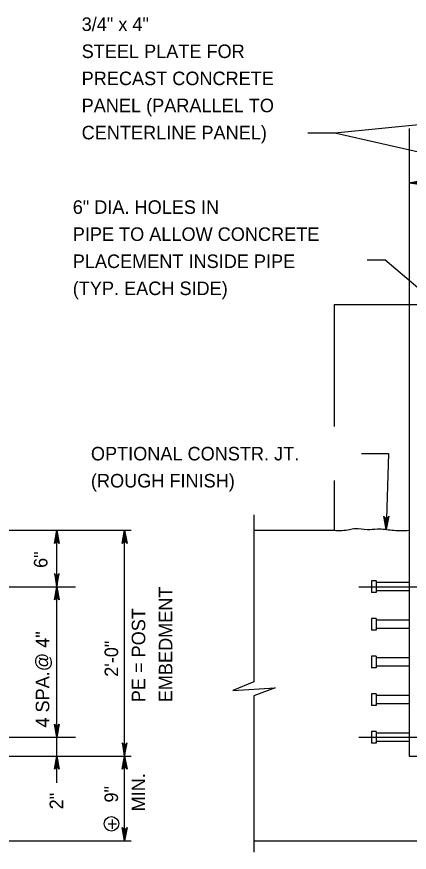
# Model space of a CAD drawing. Extents: x 3475 to 6558, y -3780 to 1166.
# Drawn here: x 4944.3 to 5033.3, y -2741.6 to -2552.1 of the extents above; entities that cross this region are included whole.
import ezdxf

# ---------------------------------------------------------------- set-up
doc = ezdxf.new("R2010")
doc.units = 0
doc.layers.add('1', color=7, linetype='Continuous')

msp = doc.modelspace()

# ---------------------------------------------------------------- linework, layer by layer
at = {"layer": '1'}
for p, q in [((5016.45, -2578.46), (5041.25, -2576)), ((5033.33, -2577.44), (5033.33, -2719.79)), ((5010.3, -2578.46), (5016.45, -2578.46)), ((5016.45, -2578.46), (5056.51, -2587.47)), ((5023.76, -2607.24), (5027.77, -2607.24)), ((5049.8, -2626.04), (5027.77, -2607.24)), ((5016.26, -2617.39), (5016.26, -2645.07)), ((5016.26, -2617.39), (5033.33, -2617.39)), ((5033.33, -2617.39), (5076, -2617.39)), ((5022.48, -2651.17), (5028.63, -2651.17)), ((5028.63, -2651.17), (5028.12, -2668.4)), ((5016.26, -2657.26), (5016.26, -2668.59)), ((4998.1, -2665.05), (4998.1, -2702.94)), ((4940.22, -2668.59), (4970.24, -2668.59)), ((4953.4, -2725.87), (4953.4, -2668.59)), ((4968.76, -2738.99), (4968.76, -2668.59)), ((4998.1, -2668.59), (5016.26, -2668.59)), ((4776.48, -2681.39), (4957.63, -2681.39)), ((5021.89, -2681.39), (5166, -2681.39)), ((5024.8, -2680.06), (5024.8, -2682.72)), ((5025.82, -2680.06), (5024.8, -2680.06)), ((5025.82, -2680.06), (5025.82, -2682.72)), ((5033.33, -2680.46), (5025.82, -2680.46)), ((5025.82, -2682.72), (5024.8, -2682.72)), ((5033.33, -2682.32), (5025.82, -2682.32)), ((5024.8, -2688.59), (5024.8, -2691.26)), ((5025.82, -2688.59), (5024.8, -2688.59)), ((5025.82, -2688.59), (5025.82, -2691.26)), ((5033.33, -2688.99), (5025.82, -2688.99)), ((5025.82, -2691.26), (5024.8, -2691.26)), ((5033.33, -2690.86), (5025.82, -2690.86)), ((5024.8, -2697.12), (5024.8, -2699.79)), ((5025.82, -2697.12), (5024.8, -2697.12)), ((5025.82, -2697.12), (5025.82, -2699.79)), ((5033.33, -2697.52), (5025.82, -2697.52)), ((5025.82, -2699.79), (5024.8, -2699.79)), ((5033.33, -2699.39), (5025.82, -2699.39)), ((4998.1, -2706.14), (4998.1, -2741.63)), ((5024.8, -2705.65), (5024.8, -2708.32)), ((5025.82, -2705.65), (5024.8, -2705.65)), ((5025.82, -2705.65), (5025.82, -2708.32)), ((5033.33, -2706.05), (5025.82, -2706.05)), ((5025.82, -2708.32), (5024.8, -2708.32)), ((5033.33, -2707.92), (5025.82, -2707.92)), ((4807.65, -2715.52), (4957.63, -2715.52)), ((5021.89, -2715.52), (5166, -2715.52)), ((5024.8, -2714.19), (5024.8, -2716.85)), ((5025.82, -2714.19), (5024.8, -2714.19)), ((5025.82, -2714.19), (5025.82, -2716.85)), ((5033.33, -2714.59), (5025.82, -2714.59)), ((5025.82, -2716.85), (5024.8, -2716.85)), ((5033.33, -2716.46), (5025.82, -2716.46)), ((4832.38, -2719.79), (4970.24, -2719.79)), ((5033.33, -2719.79), (5076, -2719.79)), ((4909.66, -2738.99), (4970.24, -2738.99)), ((4998.1, -2738.99), (5112.02, -2738.99))]:
    msp.add_line(p, q, dxfattribs=at)
for points in [[(5033.33, -2589.76), (5036.31, -2589.2), (5036.08, -2589.36), (5035.97, -2589.56), (5035.93, -2589.76), (5035.97, -2589.96), (5036.08, -2590.16), (5036.31, -2590.32), (5033.33, -2589.76), (5036.08, -2590.16), (5035.97, -2589.96), (5033.33, -2589.76), (5035.93, -2589.76), (5035.97, -2589.56), (5033.33, -2589.76), (5036.08, -2589.36)], [(5028.12, -2668.4), (5027.56, -2665.42), (5027.72, -2665.65), (5027.92, -2665.76), (5028.12, -2665.8), (5028.32, -2665.76), (5028.52, -2665.65), (5028.68, -2665.42), (5028.12, -2668.4), (5028.52, -2665.65), (5028.32, -2665.76), (5028.12, -2668.4), (5028.12, -2665.8), (5027.92, -2665.76), (5028.12, -2668.4), (5027.72, -2665.65)], [(4953.4, -2668.59), (4953.96, -2671.57), (4953.8, -2671.34), (4953.6, -2671.22), (4953.4, -2671.19), (4953.2, -2671.22), (4953, -2671.34), (4952.84, -2671.57), (4953.4, -2668.59), (4953, -2671.34), (4953.2, -2671.22), (4953.4, -2668.59), (4953.4, -2671.19), (4953.6, -2671.22), (4953.4, -2668.59), (4953.8, -2671.34)], [(4968.76, -2668.59), (4969.32, -2671.57), (4969.16, -2671.34), (4968.96, -2671.22), (4968.76, -2671.19), (4968.56, -2671.22), (4968.36, -2671.34), (4968.2, -2671.57), (4968.76, -2668.59), (4968.36, -2671.34), (4968.56, -2671.22), (4968.76, -2668.59), (4968.76, -2671.19), (4968.96, -2671.22), (4968.76, -2668.59), (4969.16, -2671.34)], [(4953.4, -2681.39), (4953.96, -2678.41), (4953.8, -2678.64), (4953.6, -2678.76), (4953.4, -2678.79), (4953.2, -2678.76), (4953, -2678.64), (4952.84, -2678.41), (4953.4, -2681.39), (4953, -2678.64), (4953.2, -2678.76), (4953.4, -2681.39), (4953.4, -2678.79), (4953.6, -2678.76), (4953.4, -2681.39), (4953.8, -2678.64)], [(4953.4, -2681.39), (4953.96, -2684.37), (4953.8, -2684.14), (4953.6, -2684.02), (4953.4, -2683.99), (4953.2, -2684.02), (4953, -2684.14), (4952.84, -2684.37), (4953.4, -2681.39), (4953, -2684.14), (4953.2, -2684.02), (4953.4, -2681.39), (4953.4, -2683.99), (4953.6, -2684.02), (4953.4, -2681.39), (4953.8, -2684.14)], [(4998.1, -2702.94), (4993.3, -2704.89), (5002.9, -2704.31), (4998.1, -2706.14)], [(4953.4, -2715.52), (4952.84, -2712.54), (4953, -2712.77), (4953.2, -2712.89), (4953.4, -2712.92), (4953.6, -2712.89), (4953.8, -2712.77), (4953.96, -2712.54), (4953.4, -2715.52), (4953.8, -2712.77), (4953.6, -2712.89), (4953.4, -2715.52), (4953.4, -2712.92), (4953.2, -2712.89), (4953.4, -2715.52), (4953, -2712.77)], [(4968.76, -2719.79), (4969.32, -2716.81), (4969.16, -2717.04), (4968.96, -2717.15), (4968.76, -2717.19), (4968.56, -2717.15), (4968.36, -2717.04), (4968.2, -2716.81), (4968.76, -2719.79), (4968.36, -2717.04), (4968.56, -2717.15), (4968.76, -2719.79), (4968.76, -2717.19), (4968.96, -2717.15), (4968.76, -2719.79), (4969.16, -2717.04)], [(4953.4, -2719.79), (4953.96, -2722.77), (4953.8, -2722.54), (4953.6, -2722.42), (4953.4, -2722.39), (4953.2, -2722.42), (4953, -2722.54), (4952.84, -2722.77), (4953.4, -2719.79), (4953, -2722.54), (4953.2, -2722.42), (4953.4, -2719.79), (4953.4, -2722.39), (4953.6, -2722.42), (4953.4, -2719.79), (4953.8, -2722.54)], [(4968.76, -2719.79), (4969.32, -2722.77), (4969.16, -2722.54), (4968.96, -2722.42), (4968.76, -2722.39), (4968.56, -2722.42), (4968.36, -2722.54), (4968.2, -2722.77), (4968.76, -2719.79), (4968.36, -2722.54), (4968.56, -2722.42), (4968.76, -2719.79), (4968.76, -2722.39), (4968.96, -2722.42), (4968.76, -2719.79), (4969.16, -2722.54)], [(4968.76, -2738.99), (4968.2, -2736.01), (4968.36, -2736.24), (4968.56, -2736.36), (4968.76, -2736.39), (4968.96, -2736.36), (4969.16, -2736.24), (4969.32, -2736.01), (4968.76, -2738.99), (4969.16, -2736.24), (4968.96, -2736.36), (4968.76, -2738.99), (4968.76, -2736.39), (4968.56, -2736.36), (4968.76, -2738.99), (4968.36, -2736.24)]]:
    msp.add_lwpolyline(points, dxfattribs=at)
msp.add_circle((4965.78, -2735.17), 1.65, dxfattribs=at)
msp.add_spline([(5016.26, -2668.59), (5019.79, -2668.41), (5021.03, -2668.16), (5023.76, -2668.41), (5026.12, -2668.27), (5027.78, -2668.37), (5031.08, -2668.66), (5033.33, -2668.59)], degree=3, dxfattribs=at)

# ---------------------------------------------------------------- texts
for s, height, p in [('3/4" x 4"', 3.072, (4959.03, -2555.33)), ('STEEL PLATE FOR ', 3.072, (4959.03, -2561.47)), ('PRECAST CONCRETE', 3.072, (4959.03, -2567.62)), ('PANEL (PARALLEL TO', 3.072, (4959.03, -2573.76)), ('CENTERLINE PANEL)', 3.072, (4959.03, -2579.91)), ('6" DIA. HOLES IN ', 3.072, (4957.01, -2596.81)), ('PIPE TO ALLOW CONCRETE', 3.072, (4957.01, -2602.95)), ('PLACEMENT INSIDE PIPE', 3.072, (4957.01, -2609.1)), ('(TYP. EACH SIDE)', 3.072, (4957.01, -2615.24)), ('OPTIONAL CONSTR. JT.', 3.072, (4961.13, -2652.74)), ('(ROUGH FINISH)', 3.072, (4961.13, -2658.88)), ('+', 3.07, (4964.77, -2736.71))]:
    msp.add_text(s, height=height, dxfattribs=at).set_placement(p)
for s, p in [('6"', (4951.27, -2677.13)), ('EMBEDMENT', (4979.59, -2707.59)), ('PE = POST', (4973.45, -2707.59)), ('4 SPA.@ 4"', (4951.68, -2713.34)), ('2\'-0"', (4967.3, -2701.81)), ('MIN.', (4973.43, -2732.35)), ('9"', (4967.28, -2730.34)), ('2"', (4954.84, -2731.89))]:
    msp.add_text(s, height=3.072, rotation=90, dxfattribs=at).set_placement(p)

doc.saveas('drawing.dxf')
